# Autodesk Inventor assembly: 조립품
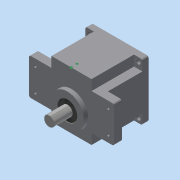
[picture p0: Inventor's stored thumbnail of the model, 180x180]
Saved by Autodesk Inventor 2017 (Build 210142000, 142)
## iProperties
Part Number: 조립품
Material: 일반
Document SubType Name: Assembly
Designer: user
Author: user
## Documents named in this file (10)
- C:\Users\user\Desktop\700116V1012\조립품.iam
- C:\Users\user\Desktop\700116V1012\메인 축.ipt
- C:\Users\user\Desktop\700116V1012\베어링 608.ipt
- C:\Users\user\Desktop\700116V1012\베어링 6003.ipt
- C:\Users\user\Desktop\700116V1012\본체.ipt
- C:\Users\user\Desktop\700116V1012\볼트 M4.ipt
- C:\Users\user\Desktop\700116V1012\서브 축.ipt
- C:\Users\user\Desktop\700116V1012\오일 실 8 22 7.ipt
- C:\Users\user\Desktop\700116V1012\오일 실 17 32 8.ipt
- C:\Users\user\Desktop\700116V1012\커버.ipt
